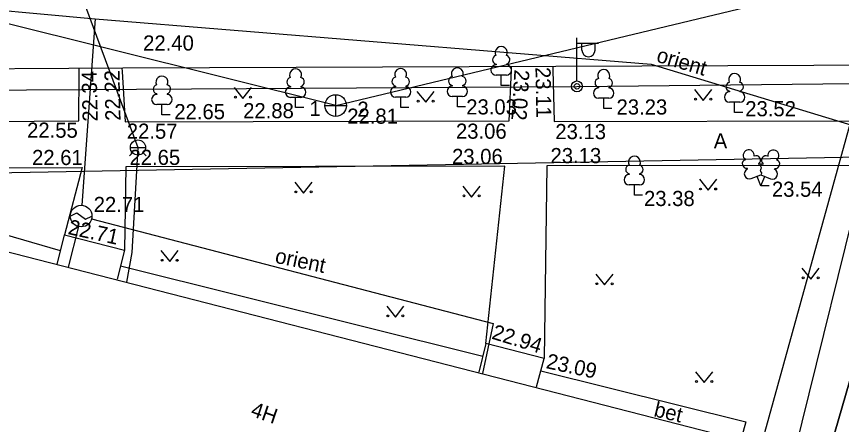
# Model space of a CAD drawing. Extents: x 714391 to 714584, y 6589993 to 6590151.
# Drawn here: x 714490.89 to 714529.01, y 6590074.53 to 6590093.39 of the extents above; entities that cross this region are included whole.
import ezdxf

# ---------------------------------------------------------------- set-up
doc = ezdxf.new("R2010")
doc.units = 0
for name, color, linetype in [('HALJASTUS', 7, 'Continuous'), ('HOONE', 7, 'Continuous'), ('HOONEDET', 7, 'Continuous'), ('KKAEV', 7, 'Continuous'), ('KORGUS', 7, 'Continuous'), ('KTRASS', 7, 'Continuous'), ('MPKAABEL', 7, 'Continuous'), ('POST', 7, 'Continuous'), ('PUU', 7, 'Continuous'), ('SITRASS', 7, 'Continuous'), ('SKTRASS', 7, 'Continuous'), ('TEE', 7, 'Continuous'), ('TORU NR', 7, 'Continuous'), ('TTRASS', 7, 'Continuous'), ('VKAEV', 7, 'Continuous'), ('VTRASS', 7, 'Continuous'), ('Слой 1', 7, 'Continuous')]:
    doc.layers.add(name, color=color, linetype=linetype)

msp = doc.modelspace()

# ---------------------------------------------------------------- linework, layer by layer
at = {"layer": 'HALJASTUS'}
for p, q in [((714500.954, 6590090.112), (714501.359, 6590089.607)), ((714501.359, 6590089.607), (714501.754, 6590090.112)), ((714509.397, 6590089.931), (714509.802, 6590089.426)), ((714509.802, 6590089.426), (714510.197, 6590089.931)), ((714522.221, 6590090.021), (714522.626, 6590089.516)), ((714522.626, 6590089.516), (714523.021, 6590090.021)), ((714503.753, 6590085.732), (714504.158, 6590085.227)), ((714504.158, 6590085.227), (714504.553, 6590085.732)), ((714522.447, 6590085.867), (714522.852, 6590085.362)), ((714522.852, 6590085.362), (714523.247, 6590085.867)), ((714511.519, 6590085.551), (714511.924, 6590085.046)), ((714511.924, 6590085.046), (714512.319, 6590085.551)), ((714497.567, 6590082.571), (714497.972, 6590082.066)), ((714497.972, 6590082.066), (714498.367, 6590082.571)), ((714517.66, 6590081.487), (714518.065, 6590080.982)), ((714518.065, 6590080.982), (714518.46, 6590081.487)), ((714527.188, 6590081.758), (714527.593, 6590081.253)), ((714527.593, 6590081.253), (714527.988, 6590081.758)), ((714507.998, 6590079.997), (714508.403, 6590079.492)), ((714508.403, 6590079.492), (714508.798, 6590079.997)), ((714522.266, 6590076.972), (714522.671, 6590076.467)), ((714522.671, 6590076.467), (714523.066, 6590076.972))]:
    msp.add_line(p, q, dxfattribs=at)
for centre, radius in [((714501.006, 6590089.662), 0.0428), ((714501.706, 6590089.662), 0.0452), ((714509.449, 6590089.481), 0.0428), ((714510.149, 6590089.481), 0.0452), ((714522.273, 6590089.572), 0.0428), ((714522.973, 6590089.572), 0.0452), ((714503.805, 6590085.282), 0.0428), ((714504.505, 6590085.282), 0.0452), ((714522.499, 6590085.418), 0.0428), ((714523.199, 6590085.418), 0.0452), ((714511.571, 6590085.102), 0.0428), ((714512.271, 6590085.102), 0.0452), ((714497.619, 6590082.121), 0.0428), ((714498.319, 6590082.121), 0.0452), ((714517.712, 6590081.038), 0.0428), ((714518.412, 6590081.038), 0.0452), ((714527.24, 6590081.309), 0.0428), ((714527.94, 6590081.309), 0.0452), ((714508.05, 6590079.548), 0.0428), ((714508.75, 6590079.548), 0.0452), ((714522.318, 6590076.522), 0.0428), ((714523.018, 6590076.522), 0.0452)]:
    msp.add_circle(centre, radius, dxfattribs=at)
at = {"layer": 'HOONE'}
for p, q in [((714494.525, 6590093.286), (714493.915, 6590084.667)), ((714493.38, 6590084.168), (714493.68, 6590084.318)), ((714493.68, 6590084.318), (714494.08, 6590084.018)), ((714494.08, 6590084.018), (714494.38, 6590084.168)), ((714493.757, 6590083.683), (714493.282, 6590081.802))]:
    msp.add_line(p, q, dxfattribs=at)
for points in [[(714462.976, 6590094.666), (714464.039, 6590094.043), (714487.101, 6590093.963), (714494.525, 6590093.286), (714520.217, 6590091.196), (714543.829, 6590084.007)], [(714520.618, 6590063.399), (714481.385, 6590073.617), (714484.074, 6590084.17), (714523.648, 6590073.994), (714520.618, 6590063.399)], [(714494.364, 6590084.042), (714512.912, 6590079.193), (714512.422, 6590076.881)], [(714492.767, 6590081.931), (714493.109, 6590083.292), (714495.884, 6590082.598), (714495.548, 6590081.252)], [(714514.927, 6590076.269), (714515.277, 6590077.587), (714512.583, 6590078.272), (714512.259, 6590076.95)]]:
    msp.add_lwpolyline(points, dxfattribs=at)
msp.add_circle((714493.88, 6590084.168), 0.5, dxfattribs=at)
at = {"layer": 'KKAEV'}
for p, q in [((714505.642, 6590088.775), (714505.642, 6590089.775)), ((714505.142, 6590089.275), (714506.142, 6590089.275))]:
    msp.add_line(p, q, dxfattribs=at)
msp.add_circle((714505.642, 6590089.275), 0.5, dxfattribs=at)
at = {"layer": 'KTRASS'}
for q in [(714467.741, 6590098.726), (714540.165, 6590097.573)]:
    msp.add_line((714505.642, 6590089.275), q, dxfattribs=at)
at = {"layer": 'MPKAABEL'}
msp.add_lwpolyline([(714460.809, 6590089.818), (714516.791, 6590090.163), (714543.78, 6590090.458), (714574.561, 6590090.139)], dxfattribs=at)
at = {"layer": 'POST'}
for p, q in [((714516.791, 6590090.413), (714516.791, 6590092.413)), ((714516.791, 6590092.163), (714517.791, 6590092.163)), ((714517.018, 6590091.842), (714517.018, 6590092.163)), ((714517.63, 6590091.842), (714517.63, 6590092.163)), ((714516.791, 6590090.163), (714516.791, 6590090.163))]:
    msp.add_line(p, q, dxfattribs=at)
for radius in [0.25, 0.127]:
    msp.add_circle((714516.791, 6590090.163), radius, dxfattribs=at)
msp.add_arc((714517.324, 6590091.842), 0.306, 180, 0, dxfattribs=at)
at = {"layer": 'PUU'}
for p, q in [((714513.05, 6590091.186), (714513.05, 6590091.156)), ((714513.53, 6590091.186), (714513.53, 6590091.156)), ((714513.53, 6590090.681), (714513.05, 6590090.681)), ((714513.29, 6590090.206), (714513.29, 6590090.681)), ((714511.023, 6590090.201), (714511.023, 6590090.171)), ((714511.503, 6590090.201), (714511.503, 6590090.171)), ((714513.67, 6590090.206), (714513.29, 6590090.206)), ((714497.371, 6590089.825), (714497.371, 6590089.795)), ((714497.851, 6590089.825), (714497.851, 6590089.795)), ((714503.55, 6590090.159), (714503.55, 6590090.129)), ((714504.03, 6590090.159), (714504.03, 6590090.129)), ((714508.405, 6590090.173), (714508.405, 6590090.143)), ((714508.885, 6590090.173), (714508.885, 6590090.143)), ((714517.788, 6590090.12), (714517.788, 6590090.09)), ((714518.268, 6590090.12), (714518.268, 6590090.09)), ((714523.837, 6590089.937), (714523.837, 6590089.907)), ((714524.317, 6590089.937), (714524.317, 6590089.907)), ((714504.03, 6590089.654), (714503.55, 6590089.654)), ((714503.79, 6590089.179), (714503.79, 6590089.654)), ((714508.885, 6590089.668), (714508.405, 6590089.668)), ((714508.645, 6590089.193), (714508.645, 6590089.668)), ((714511.503, 6590089.696), (714511.023, 6590089.696)), ((714511.263, 6590089.221), (714511.263, 6590089.696)), ((714518.268, 6590089.615), (714517.788, 6590089.615)), ((714518.028, 6590089.14), (714518.028, 6590089.615)), ((714524.317, 6590089.432), (714523.837, 6590089.432)), ((714524.077, 6590088.957), (714524.077, 6590089.432)), ((714497.851, 6590089.32), (714497.371, 6590089.32)), ((714497.611, 6590088.845), (714497.611, 6590089.32)), ((714504.17, 6590089.179), (714503.79, 6590089.179)), ((714509.025, 6590089.193), (714508.645, 6590089.193)), ((714511.643, 6590089.221), (714511.263, 6590089.221)), ((714518.408, 6590089.14), (714518.028, 6590089.14)), ((714497.991, 6590088.845), (714497.611, 6590088.845)), ((714524.457, 6590088.957), (714524.077, 6590088.957)), ((714524.672, 6590086.342), (714524.657, 6590086.382)), ((714525.202, 6590086.552), (714525.187, 6590086.587)), ((714525.387, 6590086.547), (714525.402, 6590086.587)), ((714525.912, 6590086.332), (714525.927, 6590086.372)), ((714519.205, 6590086.115), (714519.205, 6590086.085)), ((714519.685, 6590086.115), (714519.685, 6590086.085)), ((714524.847, 6590085.897), (714525.292, 6590086.072)), ((714525.287, 6590085.562), (714525.112, 6590086.002)), ((714525.287, 6590085.562), (714525.467, 6590086.002)), ((714525.292, 6590086.072), (714525.732, 6590085.892)), ((714519.685, 6590085.61), (714519.205, 6590085.61)), ((714519.445, 6590085.135), (714519.445, 6590085.61)), ((714525.667, 6590085.562), (714525.287, 6590085.562)), ((714519.825, 6590085.135), (714519.445, 6590085.135))]:
    msp.add_line(p, q, dxfattribs=at)
msp.add_lwpolyline([(714525.292, 6590086.567), (714525.272, 6590086.492), (714525.272, 6590086.472), (714525.282, 6590086.442), (714525.302, 6590086.407), (714525.307, 6590086.387), (714525.292, 6590086.352), (714525.267, 6590086.302), (714525.262, 6590086.277), (714525.267, 6590086.262), (714525.277, 6590086.232), (714525.312, 6590086.172), (714525.317, 6590086.152), (714525.312, 6590086.132), (714525.297, 6590086.097), (714525.292, 6590086.072)], dxfattribs=at)
for centre, radius, start, end in [((714513.29, 6590091.726), 0.277, 332.5799, 207.4201), ((714513.1, 6590091.394), 0.212, 105.2441, 257.079), ((714513.48, 6590091.394), 0.212, 282.921, 74.7559), ((714503.79, 6590090.699), 0.277, 332.5799, 207.4201), ((714508.645, 6590090.713), 0.277, 332.5799, 207.4201), ((714511.263, 6590090.741), 0.277, 332.5799, 207.4201), ((714513.052, 6590090.919), 0.237, 90, 270), ((714513.527, 6590090.919), 0.237, 270, 90), ((714497.611, 6590090.365), 0.277, 332.5799, 207.4201), ((714503.6, 6590090.366), 0.212, 105.2441, 257.079), ((714503.98, 6590090.366), 0.212, 282.921, 74.7559), ((714508.455, 6590090.38), 0.212, 105.2441, 257.079), ((714508.835, 6590090.38), 0.212, 282.921, 74.7559), ((714511.073, 6590090.409), 0.212, 105.2441, 257.079), ((714511.453, 6590090.409), 0.212, 282.921, 74.7559), ((714518.028, 6590090.66), 0.277, 332.5799, 207.4201), ((714524.077, 6590090.477), 0.277, 332.5799, 207.4201), ((714497.421, 6590090.033), 0.212, 105.2441, 257.079), ((714497.801, 6590090.033), 0.212, 282.921, 74.7559), ((714517.838, 6590090.328), 0.212, 105.2441, 257.079), ((714518.218, 6590090.328), 0.212, 282.921, 74.7559), ((714523.887, 6590090.145), 0.212, 105.2441, 257.079), ((714524.267, 6590090.145), 0.212, 282.921, 74.7559), ((714503.552, 6590089.891), 0.237, 90, 270), ((714504.027, 6590089.891), 0.237, 270, 90), ((714508.407, 6590089.905), 0.237, 90, 270), ((714508.882, 6590089.905), 0.237, 270, 90), ((714511.025, 6590089.934), 0.237, 90, 270), ((714511.5, 6590089.934), 0.237, 270, 90), ((714517.791, 6590089.853), 0.237, 90, 270), ((714518.265, 6590089.853), 0.237, 270, 90), ((714523.84, 6590089.67), 0.237, 90, 270), ((714524.315, 6590089.67), 0.237, 270, 90), ((714497.373, 6590089.558), 0.237, 90, 270), ((714497.848, 6590089.558), 0.237, 270, 90), ((714524.73, 6590086.976), 0.256, 111.5027, 232.5173), ((714524.73, 6590086.976), 0.256, 350.4856, 111.5002), ((714525.866, 6590086.967), 0.256, 67.6168, 188.6314), ((714525.866, 6590086.967), 0.256, 306.5997, 67.6143), ((714519.445, 6590086.655), 0.277, 332.5799, 207.4201), ((714524.631, 6590086.58), 0.202, 106.2979, 277.8684), ((714525.073, 6590086.754), 0.202, 305.1345, 116.705), ((714525.52, 6590086.75), 0.202, 62.412, 233.9825), ((714525.959, 6590086.57), 0.202, 261.2486, 72.8191), ((714519.255, 6590086.323), 0.212, 105.2441, 257.079), ((714519.635, 6590086.323), 0.212, 282.921, 74.7559), ((714525.291, 6590086.329), 0.237, 66.7655, 111.5015), ((714519.207, 6590085.848), 0.237, 90, 270), ((714519.682, 6590085.848), 0.237, 270, 90), ((714524.761, 6590086.12), 0.237, 111.5014, 291.5004), ((714525.822, 6590086.112), 0.237, 247.6166, 67.6155)]:
    msp.add_arc(centre, radius, start, end, dxfattribs=at)
at = {"layer": 'SKTRASS'}
msp.add_lwpolyline([(714531.495, 6590096.001), (714522.972, 6590065.168), (714519.718, 6590053.426), (714509.807, 6590017.772), (714505.951, 6590002.864)], dxfattribs=at)
at = {"layer": 'TEE'}
msp.add_line((714495.7, 6590081.861), (714512.438, 6590077.682), dxfattribs=at)
for points in [[(714573.651, 6590091.235), (714563.941, 6590091.279), (714547.616, 6590091.212), (714515.821, 6590091.083), (714495.803, 6590091.003), (714475.803, 6590090.885), (714460.229, 6590090.83)], [(714460.229, 6590090.83), (714460.256, 6590088.179), (714460.777, 6590088.177), (714469.248, 6590088.252), (714483.421, 6590088.5), (714493.771, 6590088.564), (714493.794, 6590090.794), (714493.796, 6590090.991)], [(714495.76, 6590091.003), (714495.77, 6590090.845), (714495.918, 6590088.527), (714513.657, 6590088.563), (714513.765, 6590090.911), (714513.773, 6590091.075)], [(714515.67, 6590091.082), (714515.674, 6590090.929), (714515.742, 6590088.532), (714529.854, 6590088.565), (714544.514, 6590088.837), (714544.463, 6590091.007), (714544.458, 6590091.199)], [(714459.34, 6590064.51), (714458.67, 6590064.05), (714447.983, 6590065.15), (714447.715, 6590065.177), (714445.65, 6590065.39), (714446.67, 6590067.85), (714448.36, 6590071.52), (714451, 6590076.28), (714452.73, 6590079.02), (714455.01, 6590082.32), (714456.89, 6590084.2), (714458.87, 6590085.38), (714460.64, 6590085.94), (714462.556, 6590086.069), (714469.16, 6590086.164), (714483.473, 6590086.366), (714493.922, 6590086.42), (714493.109, 6590083.292)], [(714512.583, 6590078.272), (714513.464, 6590086.468), (714495.941, 6590086.449), (714495.884, 6590082.598)], [(714544.103, 6590084.747), (714544.474, 6590086.687), (714529.917, 6590086.508), (714515.394, 6590086.496), (714515.277, 6590077.587)], [(714492.924, 6590082.556), (714483.739, 6590085.22), (714483.316, 6590084.953), (714480.306, 6590072.893), (714485.078, 6590071.74), (714486.316, 6590069.766), (714491.895, 6590068.37), (714493.892, 6590069.273), (714504.243, 6590066.794), (714505.962, 6590064.851), (714511.02, 6590063.567), (714513.67, 6590064.358), (714521.189, 6590062.359)], [(714515.124, 6590077.012), (714524.589, 6590074.649), (714521.189, 6590062.359)]]:
    msp.add_lwpolyline(points, dxfattribs=at)
at = {"layer": 'TTRASS'}
msp.add_lwpolyline([(714510.928, 6590008.703), (714512.829, 6590017.079), (714522.511, 6590055.684), (714522.522, 6590055.681), (714534.537, 6590104.393)], dxfattribs=at)
at = {"layer": 'VKAEV'}
for p, q in [((714496.155, 6590087.34), (714496.855, 6590087.34)), ((714496.258, 6590087.093), (714496.118, 6590086.953)), ((714496.752, 6590087.093), (714496.892, 6590086.953))]:
    msp.add_line(p, q, dxfattribs=at)
msp.add_circle((714496.505, 6590087.34), 0.35, dxfattribs=at)
at = {"layer": 'VTRASS'}
for points in [[(714490.586, 6590106.186), (714490.652, 6590105.776), (714491.439, 6590101.677), (714493.283, 6590096.028), (714496.505, 6590087.34)], [(714496.505, 6590087.34), (714496.216, 6590082.477), (714495.976, 6590081.109)]]:
    msp.add_lwpolyline(points, dxfattribs=at)
at = {"layer": 'Слой 1'}
for points in [[(714478.99, 6590085.97), (714532.4, 6590086.95), (714527.28, 6590069.21), (714523.84, 6590056.54), (714478.28, 6590068.22)], [(714579.84, 6590087.07), (714574.08, 6590064.07), (714572.19, 6590056.5), (714562.09, 6590059.36), (714527.28, 6590069.21), (714532.4, 6590086.95)]]:
    msp.add_lwpolyline(points, close=True, dxfattribs=at)

# ---------------------------------------------------------------- texts
at = {"layer": 'HOONE'}
msp.add_text('4H', height=0.7, rotation=341.0277, dxfattribs=at).set_placement((714501.671, 6590074.936))
at = {"layer": 'HOONEDET'}
msp.add_text('bet', height=0.7, rotation=346.6797, dxfattribs=at).set_placement((714520.306, 6590074.916))
at = {"layer": 'KORGUS'}
for s, p in [('22.40', (714496.745, 6590091.82)), ('23.03', (714511.674, 6590088.864)), ('23.23', (714518.619, 6590088.862)), ('23.52', (714524.567, 6590088.781)), ('22.65', (714498.185, 6590088.646)), ('22.88', (714501.366, 6590088.691)), ('22.81', (714506.176, 6590088.436)), ('22.55', (714491.382, 6590087.789)), ('22.57', (714495.99, 6590087.741)), ('23.06', (714511.2, 6590087.743)), ('23.13', (714515.791, 6590087.723)), ('22.61', (714491.612, 6590086.526)), ('22.65', (714496.115, 6590086.532)), ('23.06', (714511.019, 6590086.574)), ('23.13', (714515.568, 6590086.613)), ('23.54', (714525.799, 6590085.058)), ('23.38', (714519.889, 6590084.631)), ('22.71', (714494.46, 6590084.353))]:
    msp.add_text(s, height=0.7, dxfattribs=at).set_placement(p)
for s, rotation, p in [('23.11', 271.0416, (714514.871, 6590091.05)), ('22.34', 91.3748, (714494.651, 6590088.541)), ('22.22', 91.273, (714495.703, 6590088.582)), ('23.02', 266.4835, (714513.902, 6590090.951)), ('22.71', 347.6335, (714493.236, 6590083.34)), ('22.94', 342.6933, (714512.812, 6590078.508)), ('23.09', 347.7995, (714515.328, 6590077.139))]:
    msp.add_text(s, height=0.7, rotation=rotation, dxfattribs=at).set_placement(p)
at = {"layer": 'SITRASS'}
for rotation, p in [(343.4254, (714520.418, 6590091.315)), (348.1113, (714502.801, 6590082.012))]:
    msp.add_text('orient', height=0.7, rotation=rotation, dxfattribs=at).set_placement(p)
at = {"layer": 'TEE'}
msp.add_text('A', height=0.7, dxfattribs=at).set_placement((714523.111, 6590087.293))
at = {"layer": 'TORU NR'}
for s, p in [('1', (714504.43, 6590088.789)), ('2', (714506.643, 6590088.758))]:
    msp.add_text(s, height=0.7, dxfattribs=at).set_placement(p)

doc.saveas('drawing.dxf')
